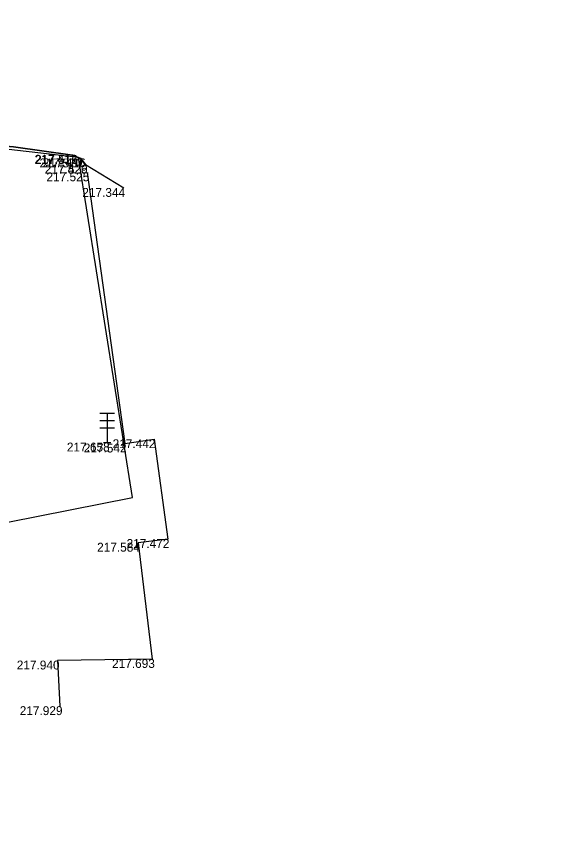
# Model space of a CAD drawing. Extents: x -599516 to -599132, y -1163668 to -1163119.
# Drawn here: x -599239.35 to -599221.12, y -1163188.81 to -1163161.2 of the extents above; entities that cross this region are included whole.
import ezdxf

# ---------------------------------------------------------------- set-up
doc = ezdxf.new("R2010")
doc.units = 0
for name, color, linetype in [('_ZEMERENI OBLAST', 7, 'Continuous'), ('Bod-oznac1', 7, 'Continuous'), ('Bod-vyska1', 7, 'Continuous'), ('Z_chodnik', 7, 'Continuous'), ('Z_komunikace', 7, 'Continuous'), ('Z_vol-lin-obrubnik', 7, 'Continuous'), ('Z_znacky-ostatni-semafor', 7, 'Continuous')]:
    doc.layers.add(name, color=color, linetype=linetype)

msp = doc.modelspace()

# ---------------------------------------------------------------- linework, layer by layer
at = {"layer": '_ZEMERENI OBLAST'}
msp.add_lwpolyline([(-599224.438, -1163495.846), (-599230.06, -1163390.87), (-599230.844, -1163376.763), (-599221.12, -1163376.319), (-599223.618, -1163350.986), (-599233.018, -1163351.47), (-599238.649, -1163235.236), (-599241.76, -1163178.74), (-599235.422, -1163177.496), (-599237.24, -1163165.98), (-599246.5, -1163164.914), (-599246.21, -1163173.61), (-599310.76, -1163161.2)], dxfattribs=at)
at = {"layer": 'Bod-oznac1'}
for p, q in [((-599237.45, -1163165.899), (-599237.45, -1163165.899)), ((-599237.448, -1163165.89), (-599237.448, -1163165.89)), ((-599237.186, -1163166.015), (-599237.186, -1163166.015)), ((-599237.18, -1163166.008), (-599237.18, -1163166.008)), ((-599237.019, -1163166.229), (-599237.019, -1163166.229)), ((-599237.011, -1163166.223), (-599237.011, -1163166.223)), ((-599236.951, -1163166.485), (-599236.951, -1163166.485)), ((-599235.714, -1163167.013), (-599235.714, -1163167.013)), ((-599234.687, -1163175.521), (-599234.687, -1163175.521)), ((-599236.271, -1163175.634), (-599236.271, -1163175.634)), ((-599235.676, -1163175.667), (-599235.676, -1163175.667)), ((-599234.224, -1163178.899), (-599234.224, -1163178.899)), ((-599235.224, -1163179.025), (-599235.224, -1163179.025)), ((-599237.959, -1163183.014), (-599237.959, -1163183.014)), ((-599234.753, -1163182.962), (-599234.753, -1163182.962)), ((-599237.879, -1163184.559), (-599237.879, -1163184.559))]:
    msp.add_line(p, q, dxfattribs=at)
at = {"layer": 'Z_chodnik'}
for points in [[(-599236.951, -1163166.485), (-599235.676, -1163175.667), (-599234.687, -1163175.521), (-599234.224, -1163178.899), (-599235.224, -1163179.025), (-599234.753, -1163182.962), (-599237.959, -1163183.014)], [(-599237.959, -1163183.014), (-599237.879, -1163184.559)]]:
    msp.add_lwpolyline(points, dxfattribs=at)
at = {"layer": 'Z_komunikace'}
msp.add_lwpolyline([(-599248.863, -1163165.054), (-599246.662, -1163165.164), (-599245.655, -1163165.229), (-599240.684, -1163165.507), (-599239.45, -1163165.606), (-599237.448, -1163165.89), (-599237.18, -1163166.008), (-599237.011, -1163166.223), (-599235.714, -1163167.013)], dxfattribs=at)
at = {"layer": 'Z_vol-lin-obrubnik'}
msp.add_lwpolyline([(-599248.863, -1163165.063), (-599247.487, -1163165.132), (-599246.662, -1163165.173), (-599245.655, -1163165.238), (-599240.685, -1163165.516), (-599239.451, -1163165.615), (-599237.45, -1163165.899), (-599237.186, -1163166.015), (-599237.019, -1163166.229)], dxfattribs=at)
at = {"layer": 'Z_znacky-ostatni-semafor'}
for p, q in [((-599236.521, -1163174.634), (-599236.021, -1163174.634)), ((-599236.271, -1163174.634), (-599236.271, -1163175.634)), ((-599236.521, -1163174.884), (-599236.021, -1163174.884)), ((-599236.521, -1163175.134), (-599236.021, -1163175.134)), ((-599236.396, -1163175.634), (-599236.146, -1163175.634))]:
    msp.add_line(p, q, dxfattribs=at)

# ---------------------------------------------------------------- texts
at = {"layer": 'Bod-vyska1'}
for s, p in [('217.412', (-599238.735, -1163166.19)), ('217.516', (-599238.714, -1163166.199)), ('217.520', (-599238.564, -1163166.315)), ('217.416', (-599238.455, -1163166.308)), ('217.426', (-599238.39, -1163166.523)), ('217.529', (-599238.387, -1163166.529)), ('217.525', (-599238.33, -1163166.785)), ('217.344', (-599237.116, -1163167.313)), ('217.442', (-599236.089, -1163175.821)), ('217.658', (-599237.639, -1163175.934)), ('217.542', (-599237.067, -1163175.967)), ('217.472', (-599235.617, -1163179.199)), ('217.584', (-599236.615, -1163179.325)), ('217.940', (-599239.336, -1163183.314)), ('217.693', (-599236.11, -1163183.262)), ('217.929', (-599239.236, -1163184.859))]:
    msp.add_text(s, height=0.3, dxfattribs=at).set_placement(p)

doc.saveas('drawing.dxf')
